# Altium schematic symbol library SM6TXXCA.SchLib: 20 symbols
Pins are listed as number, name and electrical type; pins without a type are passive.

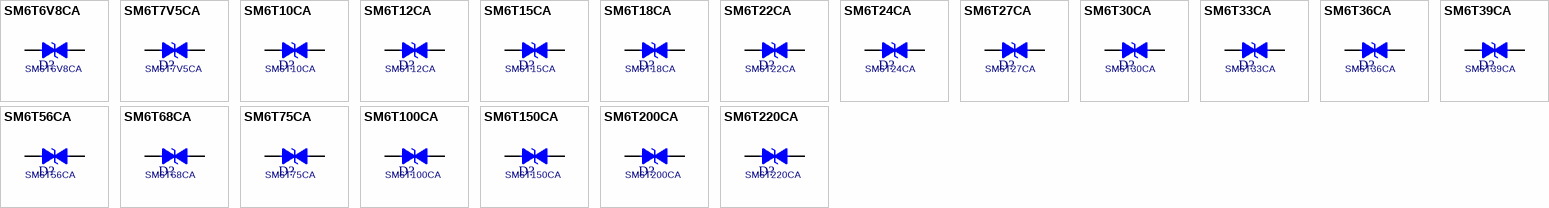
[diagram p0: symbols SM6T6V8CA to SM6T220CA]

## SM6T6V8CA
designator D?
footprint ST_SMBB
pins: 1, 2

## SM6T7V5CA
designator D?
footprint ST_SMBB
pins: 1, 2

## SM6T10CA
designator D?
footprint ST_SMBB
pins: 1, 2

## SM6T12CA
designator D?
footprint ST_SMBB
pins: 1, 2

## SM6T15CA
designator D?
footprint ST_SMBB
pins: 1, 2

## SM6T18CA
designator D?
footprint ST_SMBB
pins: 1, 2

## SM6T22CA
designator D?
footprint ST_SMBB
pins: 1, 2

## SM6T24CA
designator D?
footprint ST_SMBB
pins: 1, 2

## SM6T27CA
designator D?
footprint ST_SMBB
pins: 1, 2

## SM6T30CA
designator D?
footprint ST_SMBB
pins: 1, 2

## SM6T33CA
designator D?
footprint ST_SMBB
pins: 1, 2

## SM6T36CA
designator D?
footprint ST_SMBB
pins: 1, 2

## SM6T39CA
designator D?
footprint ST_SMBB
pins: 1, 2

## SM6T56CA
designator D?
footprint ST_SMBB
pins: 1, 2

## SM6T68CA
designator D?
footprint ST_SMBB
pins: 1, 2

## SM6T75CA
designator D?
footprint ST_SMBB
pins: 1, 2

## SM6T100CA
designator D?
footprint ST_SMBB
pins: 1, 2

## SM6T150CA
designator D?
footprint ST_SMBB
pins: 1, 2

## SM6T200CA
designator D?
footprint ST_SMBB
pins: 1, 2

## SM6T220CA
designator D?
footprint ST_SMBB
pins: 1, 2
